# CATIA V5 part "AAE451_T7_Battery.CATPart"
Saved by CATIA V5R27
Part number: AAE451_T7_Battery
Bounding box of the stored display mesh (mm): x 0 to 142.55, y 0 to 41.04, z 0 to 49.48
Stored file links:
  W:\pu.data\Desktop\Senior Design\AAE451_T7_Battery.CATPart
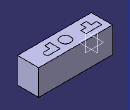
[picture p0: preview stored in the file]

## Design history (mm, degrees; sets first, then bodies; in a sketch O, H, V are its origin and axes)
Body1 (main body)
  Sketch1 on xy-plane, origin (0, 0, 0), H (1, 0, 0), V (0, 1, 0)
    line L1 (0, 0) -> (142.55, 0)
    line L2 (142.55, 0) -> (142.55, 41.04)
    line L3 (142.55, 41.04) -> (0, 41.04)
    line L4 (0, 41.04) -> (0, 0)
    length L1 = 142.55
    length L4 = 41.04
    horizontal: L1 H, L3 H
    vertical: L2 V, L4 V
  Pad1 "BATTERY": profile Sketch1, direction (0, 0, 1), length 49.48
  Sketch2 on end face of Pad1, origin (0, 0, 49.48), H (1, 0, 0), V (0, 1, 0)
    line L1 (20, 30) -> (40, 30)
    line L2 (40, 30) -> (40, 20)
    line L3 (40, 20) -> (30, 20)
    line L4 (30, 20) -> (30, 10)
    line L5 (30, 10) -> (20, 10)
    line L6 (20, 10) -> (20, 20)
    point P7 (20, 20)
    line L7 (20, 20) -> (10, 20)
    line L8 (10, 20) -> (10, 30)
    line L9 (10, 30) -> (20, 30)
    circle A1 centre (70, 20) radius 10
    point P10 (70, 20)
    point P11 (100, 30)
    line L10 (100, 30) -> (110, 30)
    arc A2 centre (110, 25) radius 5 from (110, 30) to (110, 20) cw
    line L11 (110, 20) -> (100, 20)
    line L12 (100, 20) -> (100, 10)
    line L13 (100, 10) -> (90, 10)
    line L14 (90, 10) -> (90, 30)
    point P18 (90, 30)
    line L15 (90, 30) -> (100, 30)
    horizontal: L1 H, L3 H, L5 H, L7 H, L9 H, L10 H, L13 H, L15 H
    vertical: L2 V, L4 V, L6 V, L8 V, L12 V, L14 V
    coincidence: P7 L3, P10 L3, P11 L1, P18 L1
    tangency: A1 L5, A2 L10, L11 A2
  Pocket1 "TOP.Label": profile Sketch2, direction (0, 0, -1), length 0.05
